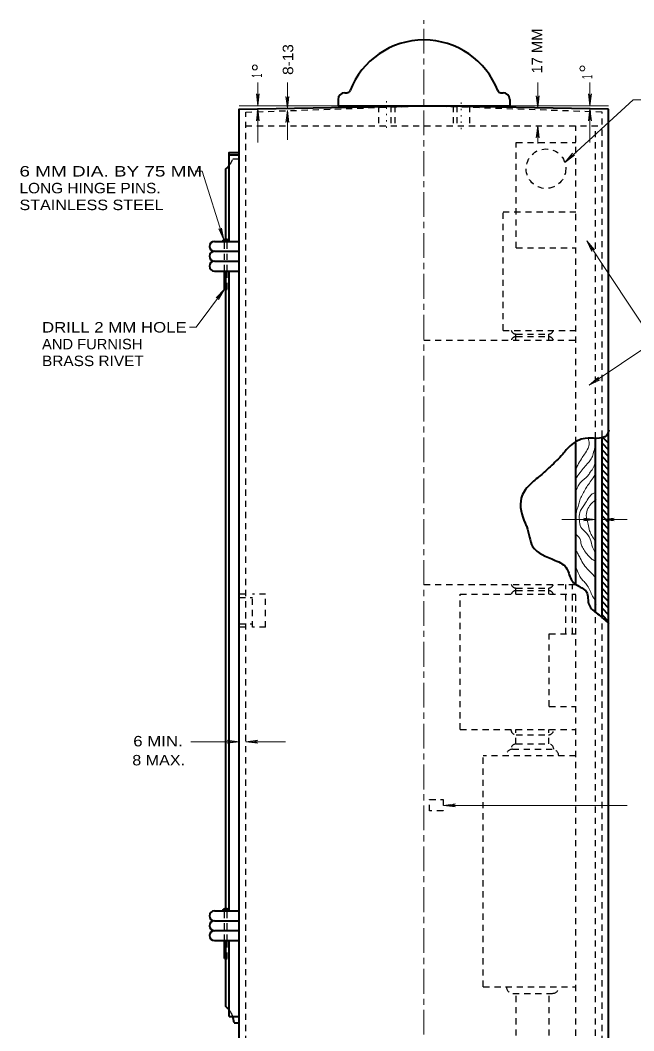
# Model space of a CAD drawing. Extents: x 312583 to 312853, y 144419 to 144586.
# Drawn here: x 312672.1 to 312716.7, y 144456.3 to 144529.7 of the extents above; entities that cross this region are included whole.
import ezdxf

# ---------------------------------------------------------------- set-up
doc = ezdxf.new("R2010")
doc.units = 0
doc.header["$LTSCALE"] = 0.3
for name, pattern in [('DOTTED', [1.5, 0.3, -1.2]), ('LONG_DASH_SHORT_DASH', [9.9, 6, -1.2, 1.5, -1.2]), ('SHORT_DASHED', [2.7, 1.5, -1.2])]:
    doc.linetypes.add(name, pattern=pattern)
doc.layers.add('1', color=7, linetype='Continuous', lineweight=40)
doc.layers.add('2', color=7, linetype='Continuous', lineweight=13)

msp = doc.modelspace()

# ---------------------------------------------------------------- linework, layer by layer
at = {"layer": '1', "linetype": 'LONG_DASH_SHORT_DASH', "lineweight": 13}
msp.add_line((312701.4426, 144444.1359), (312701.4426, 144529.7113), dxfattribs=at)
at = {"layer": '1'}
for p, q in [((312695.6926, 144524.4443), (312695.8613, 144524.4443)), ((312707.0316, 144524.4443), (312707.1926, 144524.4443)), ((312695.2173, 144523.9613), (312695.2173, 144523.4859)), ((312707.6756, 144523.9613), (312707.6756, 144523.4859)), ((312695.2173, 144523.4859), (312707.6756, 144523.4859)), ((312695.2173, 144523.4859), (312707.6756, 144523.4859)), ((312714.8593, 144523.2483), (312701.4426, 144523.4859)), ((312714.8593, 144446.5586), (312714.8593, 144523.2483)), ((312687.313, 144519.9363), (312688.026, 144519.9363)), ((312687.658, 144520.1126), (312688.026, 144520.1126)), ((312687.0676, 144513.6419), (312687.0676, 144518.9166)), ((312686.232, 144513.6419), (312688.026, 144513.6419)), ((312686.232, 144512.9213), (312688.026, 144512.9213)), ((312686.232, 144512.2083), (312688.026, 144512.2083)), ((312686.232, 144511.4876), (312688.026, 144511.4876)), ((312686.968, 144510.1766), (312686.968, 144511.4876)), ((312687.0676, 144465.0046), (312687.0676, 144511.4876)), ((312687.313, 144465.0046), (312687.313, 144511.4876)), ((312686.968, 144510.1766), (312687.1443, 144510.1766)), ((312714.384, 144486.3256), (312714.384, 144499.4509)), ((312714.384, 144499.4509), (312714.8593, 144498.9756)), ((312712.4673, 144488.7253), (312712.4673, 144498.9909)), ((312713.901, 144486.7396), (312713.901, 144499.3359)), ((312714.384, 144498.9756), (312714.8593, 144498.4926)), ((312714.384, 144498.4926), (312714.8593, 144498.0173)), ((312714.384, 144498.0173), (312714.8593, 144497.5343)), ((312714.384, 144497.5343), (312714.8593, 144497.0589)), ((312714.384, 144497.0589), (312714.8593, 144496.5759)), ((312714.384, 144496.5759), (312714.8593, 144496.1006)), ((312714.384, 144496.1006), (312714.8593, 144495.6176)), ((312714.384, 144495.6176), (312714.8593, 144495.1423)), ((312714.384, 144495.1423), (312714.8593, 144494.6593)), ((312714.384, 144494.6593), (312714.8593, 144494.1839)), ((312714.384, 144494.1839), (312714.8593, 144493.7009)), ((312714.384, 144493.7009), (312714.8593, 144493.2256)), ((312714.384, 144493.2256), (312714.8593, 144492.7426)), ((312714.384, 144492.7426), (312714.8593, 144492.2673)), ((312714.384, 144492.2673), (312714.8593, 144491.7843)), ((312714.384, 144491.7843), (312714.8593, 144491.3089)), ((312714.384, 144491.3089), (312714.8593, 144490.8259)), ((312714.384, 144490.8259), (312714.8593, 144490.3506)), ((312714.384, 144490.3506), (312714.8593, 144489.8676)), ((312714.384, 144489.8676), (312714.8593, 144489.3923)), ((312714.384, 144489.3923), (312714.8593, 144488.9093)), ((312714.384, 144488.9093), (312714.8593, 144488.4339)), ((312714.384, 144488.4339), (312714.8593, 144487.9509)), ((312714.384, 144487.9509), (312714.8593, 144487.4756)), ((312714.384, 144487.4756), (312714.8593, 144486.9926)), ((312714.384, 144486.9926), (312714.8593, 144486.5173)), ((312714.384, 144486.5173), (312714.8593, 144486.0343)), ((312686.232, 144465.0046), (312688.026, 144465.0046)), ((312686.232, 144464.2916), (312688.026, 144464.2916)), ((312686.232, 144463.5709), (312688.026, 144463.5709)), ((312686.232, 144462.8503), (312688.026, 144462.8503)), ((312686.968, 144461.5393), (312686.968, 144462.8503)), ((312687.0676, 144458.0586), (312687.0676, 144462.8503)), ((312687.313, 144457.3379), (312687.313, 144462.8503)), ((312686.968, 144461.5393), (312687.1443, 144461.5393)), ((312687.313, 144457.3379), (312688.026, 144457.3379)), ((312687.658, 144456.8626), (312688.026, 144456.8626))]:
    msp.add_line(p, q, dxfattribs=at)
at = {"layer": '1', "linetype": 'DOTTED', "lineweight": 13}
for p, q in [((312698.7363, 144523.8386), (312698.7363, 144521.6613)), ((312704.1566, 144523.7389), (312704.1566, 144521.6613))]:
    msp.add_line(p, q, dxfattribs=at)
at = {"layer": '1', "linetype": 'SHORT_DASHED', "lineweight": 25}
for p, q in [((312688.509, 144523.0336), (312701.4426, 144523.4859)), ((312688.509, 144446.5586), (312688.509, 144523.0336)), ((312698.1383, 144523.4859), (312698.1383, 144522.0446)), ((312699.0506, 144523.4859), (312699.0506, 144522.0446)), ((312699.3343, 144523.4859), (312699.3343, 144522.0446)), ((312714.384, 144523.0336), (312701.4426, 144523.4859)), ((312703.5586, 144523.4859), (312703.5586, 144522.0446)), ((312703.8423, 144523.4859), (312703.8423, 144522.0446)), ((312704.7546, 144523.4859), (312704.7546, 144522.0446)), ((312714.384, 144499.4509), (312714.384, 144523.0336)), ((312688.509, 144522.0446), (312714.384, 144522.0446)), ((312712.4673, 144498.9909), (312712.4673, 144522.0446)), ((312713.901, 144499.3359), (312713.901, 144522.0446)), ((312687.5583, 144519.6296), (312688.026, 144519.6296)), ((312707.1926, 144515.7963), (312712.4673, 144515.7963)), ((312707.1926, 144507.1713), (312707.1926, 144515.7963)), ((312686.968, 144511.4876), (312686.968, 144513.6419)), ((312687.1443, 144511.4876), (312687.1443, 144513.6419)), ((312708.151, 144513.1666), (312712.4673, 144513.1666)), ((312687.1443, 144510.1766), (312687.1443, 144511.4876)), ((312707.1926, 144507.1713), (312712.4673, 144507.1713)), ((312708.1203, 144506.4583), (312708.1203, 144507.1713)), ((312708.151, 144506.9029), (312710.4816, 144506.9029)), ((312708.151, 144506.7266), (312710.4816, 144506.7266)), ((312710.5123, 144506.4583), (312710.5123, 144507.1713)), ((312701.4426, 144506.4583), (312712.4673, 144506.4583)), ((312701.4426, 144488.7253), (312712.4673, 144488.7253)), ((312708.1203, 144488.0046), (312708.1203, 144488.7253)), ((312708.151, 144488.4569), (312710.4816, 144488.4569)), ((312710.5123, 144488.0046), (312710.5123, 144488.7253)), ((312711.7466, 144485.1296), (312711.7466, 144488.7253)), ((312712.2296, 144485.1296), (312712.2296, 144488.7253)), ((312688.509, 144488.0046), (312688.026, 144488.0046)), ((312688.026, 144487.7669), (312688.9843, 144487.7669)), ((312688.9843, 144485.6126), (312688.9843, 144488.0046)), ((312689.9426, 144488.0046), (312688.9843, 144488.0046)), ((312689.9426, 144485.6126), (312689.9426, 144488.0046)), ((312704.08, 144488.0046), (312712.4673, 144488.0046)), ((312704.08, 144478.1836), (312704.08, 144488.0046)), ((312708.151, 144488.2806), (312710.4816, 144488.2806)), ((312712.4673, 144453.5046), (312712.4673, 144487.9739)), ((312713.901, 144453.5046), (312713.901, 144486.7396)), ((312714.384, 144446.5586), (312714.384, 144486.3256)), ((312688.026, 144485.8503), (312688.9843, 144485.8503)), ((312688.509, 144485.6126), (312688.026, 144485.6126)), ((312689.9426, 144485.6126), (312688.9843, 144485.6126)), ((312710.5506, 144479.8626), (312710.5506, 144485.1296)), ((312710.5506, 144485.1296), (312712.4673, 144485.1296)), ((312710.5506, 144479.8626), (312712.4673, 144479.8626)), ((312704.08, 144478.1836), (312712.4673, 144478.1836)), ((312708.1203, 144477.1333), (312708.1203, 144478.1836)), ((312710.5123, 144477.1333), (312710.5123, 144478.1836)), ((312708.151, 144477.7926), (312710.4816, 144477.7926)), ((312707.8826, 144476.7499), (312710.7576, 144476.7499)), ((312708.151, 144477.1333), (312710.4816, 144477.1333)), ((312712.4673, 144476.2669), (312705.759, 144476.2669)), ((312705.759, 144459.4999), (312705.759, 144476.2669)), ((312686.968, 144462.8503), (312686.968, 144465.0046)), ((312687.1443, 144462.8503), (312687.1443, 144465.0046)), ((312687.1443, 144461.5393), (312687.1443, 144462.8503)), ((312705.759, 144459.4999), (312712.4673, 144459.4999)), ((312707.9133, 144459.0169), (312710.7883, 144459.0169)), ((312708.151, 144447.0416), (312708.151, 144459.0169)), ((312710.5506, 144447.0416), (312710.5506, 144459.0169))]:
    msp.add_line(p, q, dxfattribs=at)
at = {"layer": '1'}
for points in [[(312688.026, 144448.2376), (312688.026, 144523.2483), (312701.4426, 144523.4859)], [(312687.313, 144513.6419), (312687.313, 144520.1126), (312688.026, 144520.1126)]]:
    msp.add_lwpolyline(points, dxfattribs=at)
at = {"layer": '1', "linetype": 'SHORT_DASHED', "lineweight": 25}
msp.add_lwpolyline([(312708.151, 144513.1666), (312708.151, 144520.8333), (312712.4673, 144520.8333)], dxfattribs=at)
msp.add_lwpolyline([(312701.849, 144472.2726), (312701.849, 144473.1083), (312702.838, 144473.1083), (312702.838, 144472.2726)], close=True, dxfattribs=at)
msp.add_circle((312710.3091, 144518.9224), 1.4375, dxfattribs=at)
at = {"layer": '1'}
for centre, radius, start, end in [((312701.4446, 144522.5257), 5.75, 21.1002, 158.90079), ((312695.6946, 144523.9632), 0.4792, 90, 180), ((312695.8566, 144524.6819), 0.2396, 270, 338.8998), ((312707.0325, 144524.6819), 0.2396, 201.1002, 270), ((312707.1946, 144523.9632), 0.4792, 0, 90), ((312685.9644, 144520.1945), 1.6924, 310.76787, 322.61369), ((312686.231, 144513.2826), 0.3594, 90.15279, 269.84721), ((312687.0485, 144513.5578), 0.2436, 20.21131, 159.74458), ((312687.0537, 144513.5788), 0.1827, 20.21131, 159.74458), ((312687.0577, 144513.5946), 0.137, 20.21131, 159.74458), ((312687.0607, 144513.6064), 0.1028, 20.21131, 159.74458), ((312686.231, 144512.5638), 0.3594, 90.15279, 269.84721), ((312686.231, 144511.8451), 0.3594, 90.15279, 269.84721), ((312686.231, 144464.6471), 0.3594, 90.15279, 269.84721), ((312687.0485, 144464.9223), 0.2436, 20.21131, 159.74458), ((312687.0537, 144464.9434), 0.1827, 20.21131, 159.74458), ((312687.0577, 144464.9592), 0.137, 20.21131, 159.74458), ((312687.0607, 144464.971), 0.1028, 20.21131, 159.74458), ((312686.231, 144463.9284), 0.3594, 90.15279, 269.84721), ((312686.231, 144463.2096), 0.3594, 90.15279, 269.84721), ((312685.9644, 144456.7768), 1.6924, 37.36588, 49.23213), ((312685.9644, 144456.7768), 1.6924, 3.22959, 19.4309)]:
    msp.add_arc(centre, radius, start, end, dxfattribs=at)
at = {"layer": '1', "linetype": 'SHORT_DASHED', "lineweight": 25}
for centre, radius, start, end in [((312685.9644, 144520.1945), 1.6924, 322.63412, 340.56673), ((312708.153, 144507.2932), 0.3881, 198.00716, 269.9802), ((312708.153, 144506.3364), 0.3881, 90.0198, 161.99284), ((312710.4818, 144507.2932), 0.3881, 269.9802, 341.99284), ((312710.4818, 144506.3364), 0.3881, 18.00716, 90.0198), ((312708.153, 144488.8453), 0.3881, 198.00716, 269.9802), ((312710.4818, 144488.8453), 0.3881, 269.9802, 341.99284), ((312708.153, 144487.8884), 0.3881, 90.0198, 161.99284), ((312710.4818, 144487.8884), 0.3881, 18.00716, 90.0198), ((312708.153, 144478.1828), 0.3881, 180, 270), ((312710.4818, 144478.1828), 0.3881, 270, 0), ((312707.8788, 144476.2669), 0.4792, 90, 180), ((312708.153, 144476.7469), 0.3881, 90, 180), ((312710.4818, 144476.7469), 0.3881, 0, 90), ((312710.7538, 144476.2669), 0.4792, 0, 90), ((312707.9133, 144459.4961), 0.4792, 180, 270), ((312710.7883, 144459.4961), 0.4792, 270, 0), ((312685.9644, 144456.7768), 1.6924, 19.43327, 37.3863)]:
    msp.add_arc(centre, radius, start, end, dxfattribs=at)
at = {"layer": '1'}
msp.add_spline([(312714.867, 144499.9416), (312714.7136, 144499.5506), (312713.9853, 144499.3359), (312713.165, 144499.3359), (312712.0686, 144498.7916), (312711.5243, 144498.1859), (312710.612, 144497.2736), (312709.9143, 144496.6373), (312709.1016, 144495.9396), (312708.519, 144494.9966), (312708.795, 144493.1796), (312708.9176, 144492.9036), (312709.3393, 144491.4776), (312710.98, 144490.4733), (312711.831, 144489.8676), (312712.1913, 144488.9859), (312712.4673, 144488.7253), (312713.257, 144488.1733), (312713.441, 144487.2303), (312714.0466, 144486.5939), (312714.499, 144486.2259), (312714.867, 144485.8963)], degree=3, dxfattribs=at)
at = {"layer": '1', "lineweight": 13}
for points in [[(312713.3643, 144499.3359), (312713.4486, 144498.9526), (312713.3643, 144498.6229), (312713.1036, 144498.1859), (312712.8813, 144497.8486), (312712.6206, 144497.3809), (312712.475, 144497.0819)], [(312713.855, 144498.6766), (312713.74, 144498.2166), (312713.5943, 144497.8486), (312713.3796, 144497.5573), (312713.0883, 144497.2276), (312712.7816, 144496.8443), (312712.5056, 144496.4073), (312712.4903, 144496.3536)], [(312713.8703, 144497.5879), (312713.7706, 144497.2506), (312713.5253, 144496.8749), (312713.349, 144496.6143), (312712.797, 144496.1083), (312712.6206, 144495.8169), (312712.475, 144495.4489)], [(312713.8856, 144496.6986), (312713.5943, 144496.2616), (312713.3336, 144495.9013), (312713.142, 144495.5793), (312712.9273, 144495.2036), (312712.7663, 144494.8433), (312712.6666, 144494.4753), (312712.5593, 144494.1303), (312712.475, 144493.8236)], [(312713.901, 144495.4029), (312713.6096, 144495.2496), (312713.3796, 144494.9583), (312713.1036, 144494.5366), (312712.7663, 144493.9386), (312712.7356, 144493.4173), (312712.8506, 144492.8729), (312713.1266, 144492.5739), (312713.51, 144492.0219), (312713.694, 144491.4393), (312713.8856, 144491.0559)], [(312713.947, 144494.8816), (312713.4793, 144494.4446), (312713.2723, 144494.0076), (312713.2646, 144493.4556), (312713.3796, 144493.1106), (312713.4793, 144492.6276), (312713.6403, 144492.2673), (312713.855, 144491.8916), (312713.8856, 144491.8303)], [(312712.4903, 144492.3516), (312712.8123, 144491.9299), (312712.843, 144491.7306), (312712.958, 144491.4393), (312713.1726, 144491.0713), (312713.418, 144490.7799), (312713.6096, 144490.5806), (312713.8856, 144490.4349)], [(312712.4903, 144491.1863), (312712.636, 144490.9256), (312712.797, 144490.6266), (312713.0576, 144490.1589), (312713.395, 144489.7526), (312713.6863, 144489.4613), (312713.8856, 144489.2543)], [(312712.4903, 144489.9213), (312712.6973, 144489.4613), (312712.866, 144489.1546), (312713.073, 144488.9246), (312713.303, 144488.6486), (312713.5253, 144488.2653), (312713.694, 144487.8589), (312713.8243, 144487.6443), (312713.8703, 144487.4679), (312713.947, 144487.2609)]]:
    msp.add_spline(points, degree=3, dxfattribs=at)
at = {"layer": '2'}
for p, q in [((312689.383, 144523.4859), (312689.383, 144525.1803)), ((312691.5296, 144523.3096), (312691.5296, 144525.1803)), ((312709.7073, 144523.3403), (312709.7073, 144525.1803)), ((312713.5023, 144523.4859), (312713.5023, 144525.1803)), ((312689.2756, 144524.3523), (312689.383, 144524.0763)), ((312689.383, 144523.4859), (312689.2756, 144524.3523)), ((312689.4903, 144524.3523), (312689.383, 144524.0763)), ((312689.383, 144523.4859), (312689.4903, 144524.3523)), ((312713.395, 144524.3523), (312713.5023, 144524.0763)), ((312713.5023, 144523.4859), (312713.395, 144524.3523)), ((312713.6096, 144524.3523), (312713.5023, 144524.0763)), ((312713.5023, 144523.4859), (312713.6096, 144524.3523)), ((312691.4223, 144524.1759), (312691.5296, 144523.8999)), ((312691.5296, 144523.3096), (312691.4223, 144524.1759)), ((312691.637, 144524.1759), (312691.5296, 144523.8999)), ((312691.5296, 144523.3096), (312691.637, 144524.1759)), ((312709.6, 144524.2066), (312709.7073, 144523.9306)), ((312709.7073, 144523.3403), (312709.6, 144524.2066)), ((312709.8146, 144524.2066), (312709.7073, 144523.9306)), ((312709.7073, 144523.3403), (312709.8146, 144524.2066)), ((312701.4426, 144523.4859), (312688.026, 144523.4859)), ((312689.383, 144523.2713), (312689.2756, 144522.4049)), ((312689.383, 144520.8333), (312689.383, 144523.2713)), ((312689.383, 144523.2713), (312689.4903, 144522.4049)), ((312691.5296, 144523.1409), (312691.4223, 144522.2746)), ((312691.5296, 144521.0158), (312691.5296, 144523.1409)), ((312691.5296, 144523.1409), (312691.637, 144522.2746)), ((312701.4426, 144523.4859), (312714.8593, 144523.4859)), ((312713.5023, 144523.2713), (312713.395, 144522.4049)), ((312713.5023, 144520.8333), (312713.5023, 144523.2713)), ((312713.5023, 144523.2713), (312713.6096, 144522.4049)), ((312689.2756, 144522.4049), (312689.383, 144522.6809)), ((312689.4903, 144522.4049), (312689.383, 144522.6809)), ((312691.4223, 144522.2746), (312691.5296, 144522.5506)), ((312691.637, 144522.2746), (312691.5296, 144522.5506)), ((312713.395, 144522.4049), (312713.5023, 144522.6809)), ((312713.6096, 144522.4049), (312713.5023, 144522.6809)), ((312709.7073, 144522.0446), (312709.6, 144521.1783)), ((312709.6, 144521.1783), (312709.7073, 144521.4543)), ((312709.7073, 144520.7489), (312709.7073, 144522.0446)), ((312709.7073, 144522.0446), (312709.8146, 144521.1783)), ((312709.8146, 144521.1783), (312709.7073, 144521.4543)), ((312711.67, 144519.3843), (312712.2346, 144520.0519)), ((312712.2346, 144520.0519), (312712.1009, 144519.7895)), ((312711.67, 144519.3843), (312712.3796, 144519.8988)), ((312712.3796, 144519.8988), (312712.1009, 144519.7895)), ((312684.8427, 144518.7479), (312685.3426, 144518.7479)), ((312686.9066, 144513.7569), (312685.3426, 144518.7479)), ((312686.5463, 144514.5543), (312686.7303, 144514.3166)), ((312686.9066, 144513.7569), (312686.5463, 144514.5543)), ((312686.7456, 144514.6156), (312686.7303, 144514.3166)), ((312686.9066, 144513.7569), (312686.7456, 144514.6156)), ((312713.2646, 144513.6803), (312713.6499, 144512.9024)), ((312713.2646, 144513.6803), (312713.8248, 144513.0213)), ((312713.6499, 144512.9024), (312713.5886, 144513.1921)), ((312713.8248, 144513.0213), (312713.5886, 144513.1921)), ((312686.968, 144510.1766), (312684.898, 144507.4013)), ((312686.968, 144510.1766), (312686.3623, 144509.5403)), ((312686.3623, 144509.5403), (312686.6153, 144509.7013)), ((312686.968, 144510.1766), (312686.5386, 144509.4176)), ((312686.5386, 144509.4176), (312686.6153, 144509.7013)), ((312684.4086, 144507.4013), (312684.898, 144507.4013)), ((312713.4563, 144503.2076), (312714.1201, 144503.7721)), ((312714.1201, 144503.7721), (312713.9458, 144503.5355)), ((312713.4563, 144503.2076), (312714.2328, 144503.5966)), ((312714.2328, 144503.5966), (312713.9458, 144503.5355)), ((312713.0346, 144493.5476), (312713.3106, 144493.4403)), ((312713.901, 144493.4403), (312713.0346, 144493.5476)), ((312714.384, 144493.4403), (312715.2503, 144493.5476)), ((312715.2503, 144493.5476), (312714.9743, 144493.4403)), ((312711.4553, 144493.4403), (312713.901, 144493.4403)), ((312713.0346, 144493.3329), (312713.3106, 144493.4403)), ((312713.901, 144493.4403), (312713.0346, 144493.3329)), ((312714.384, 144493.4403), (312716.2163, 144493.4403)), ((312714.384, 144493.4403), (312715.2503, 144493.3329)), ((312715.2503, 144493.3329), (312714.9743, 144493.4403)), ((312687.1596, 144477.4016), (312687.4356, 144477.2943)), ((312688.026, 144477.2943), (312687.1596, 144477.4016)), ((312688.509, 144477.2943), (312689.3753, 144477.4016)), ((312689.3753, 144477.4016), (312689.0993, 144477.2943)), ((312684.5146, 144477.2943), (312688.026, 144477.2943)), ((312687.1596, 144477.1869), (312687.4356, 144477.2943)), ((312688.026, 144477.2943), (312687.1596, 144477.1869)), ((312688.509, 144477.2943), (312691.3993, 144477.2943)), ((312688.509, 144477.2943), (312689.3753, 144477.1869)), ((312689.3753, 144477.1869), (312689.0993, 144477.2943)), ((312702.8763, 144472.6713), (312703.7426, 144472.7786)), ((312702.8763, 144472.6713), (312716.2163, 144472.6713)), ((312702.8763, 144472.6713), (312703.7426, 144472.5639)), ((312703.7426, 144472.7786), (312703.4666, 144472.6713)), ((312703.7426, 144472.5639), (312703.4666, 144472.6713))]:
    msp.add_line(p, q, dxfattribs=at)
for points in [[(312711.67, 144519.3843), (312716.6329, 144523.9334), (312717.6526, 144523.9334)], [(312713.4563, 144503.2076), (312718.1501, 144506.3521), (312713.2646, 144513.6803)]]:
    msp.add_lwpolyline(points, dxfattribs=at)
for centre in [(312689.1662, 144526.2793), (312712.9523, 144526.2083)]:
    msp.add_circle(centre, 0.1797, dxfattribs=at)

# ---------------------------------------------------------------- texts
for s, width, p in [('17 MM', 1.05, (312710.0421, 144525.8395)), ('8-13', 1.1, (312691.9525, 144525.7361)), ('1', 0.5, (312689.6967, 144525.5425)), ('1', 0.5, (312713.6753, 144525.4496))]:
    msp.add_text(s, height=0.76, rotation=90, dxfattribs=dict(at, width=width)).set_placement(p)
for s, width, p in [('6 MM DIA. BY 75 MM ', 1.35, (312672.0735, 144518.3559)), ('LONG HINGE PINS.', 1.1, (312672.0735, 144517.1359)), ('STAINLESS STEEL', 1.15, (312672.0735, 144515.9159)), ('DRILL 2 MM HOLE', 1.2, (312673.7104, 144507.0227)), ('AND FURNISH', 1.05, (312673.7104, 144505.8027)), ('BRASS RIVET', 1.1, (312673.7104, 144504.5827)), ('6 MIN.', 1.2, (312680.3361, 144476.956)), ('8 MAX.', 1.15, (312680.2653, 144475.576))]:
    msp.add_text(s, height=0.76, dxfattribs=dict(at, width=width)).set_placement(p)

doc.saveas('drawing.dxf')
